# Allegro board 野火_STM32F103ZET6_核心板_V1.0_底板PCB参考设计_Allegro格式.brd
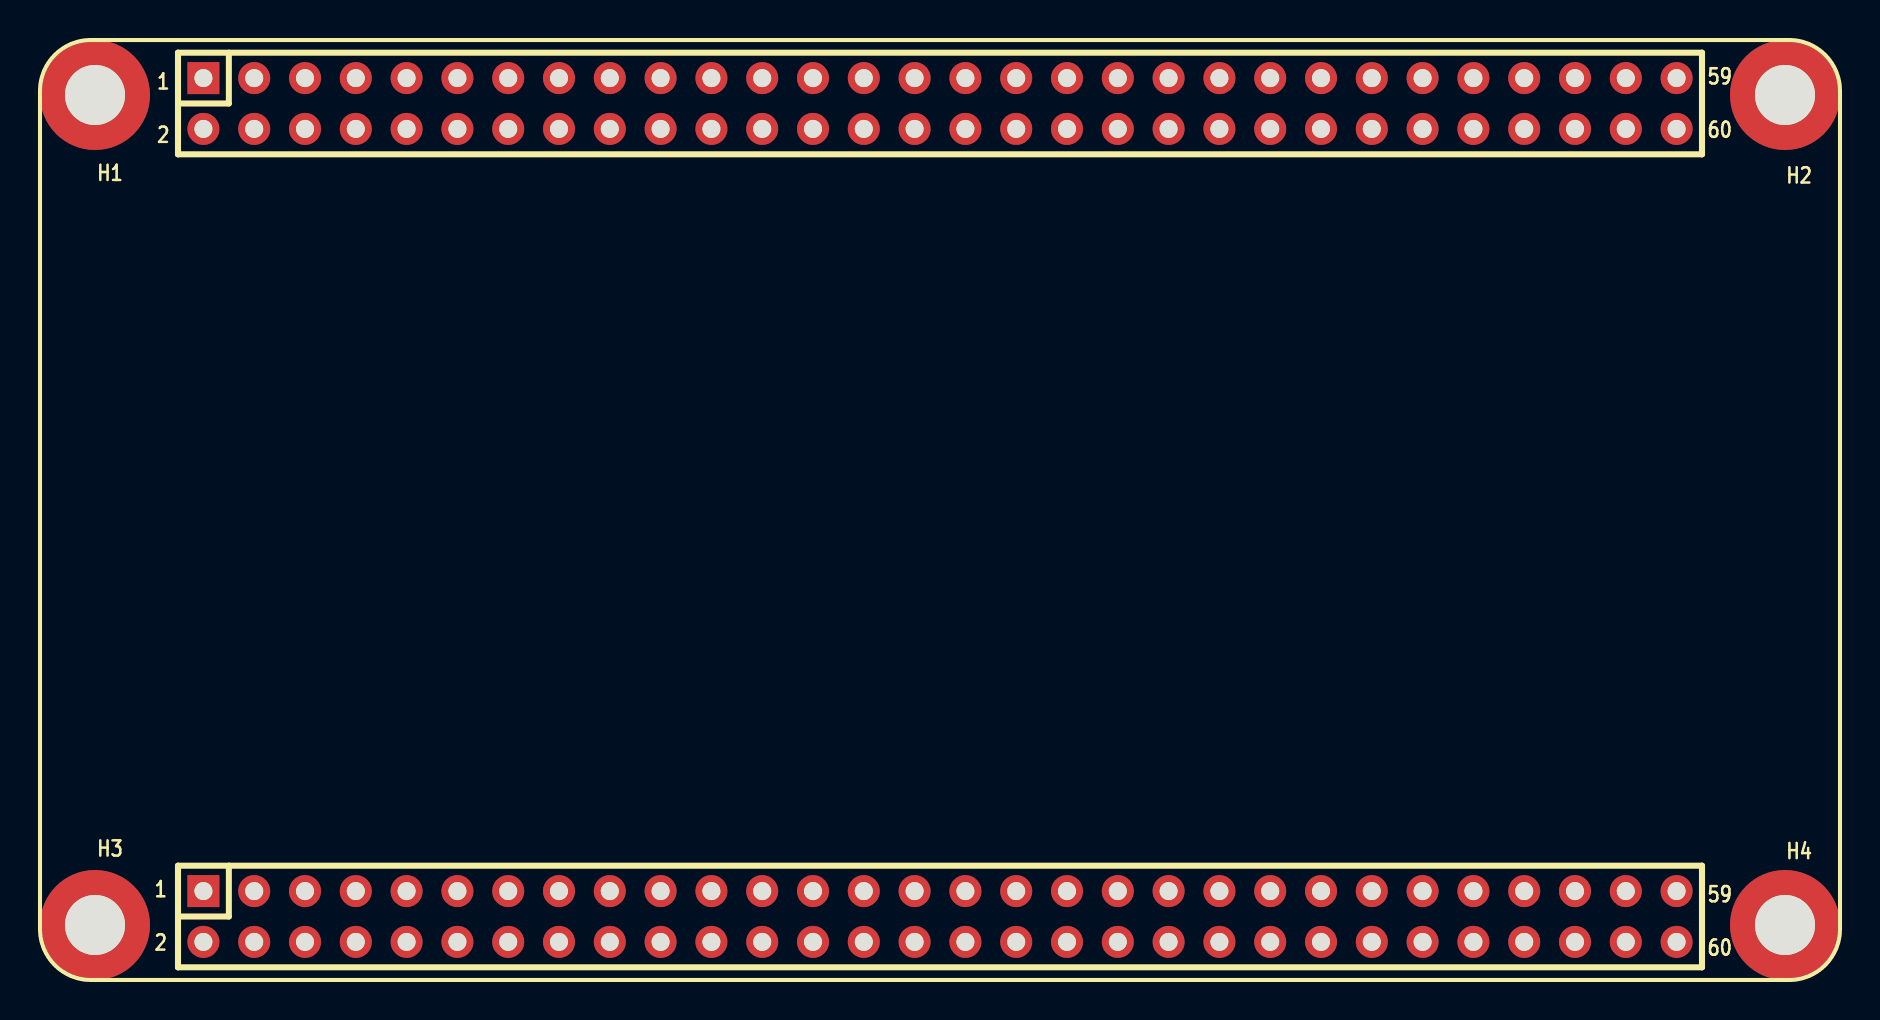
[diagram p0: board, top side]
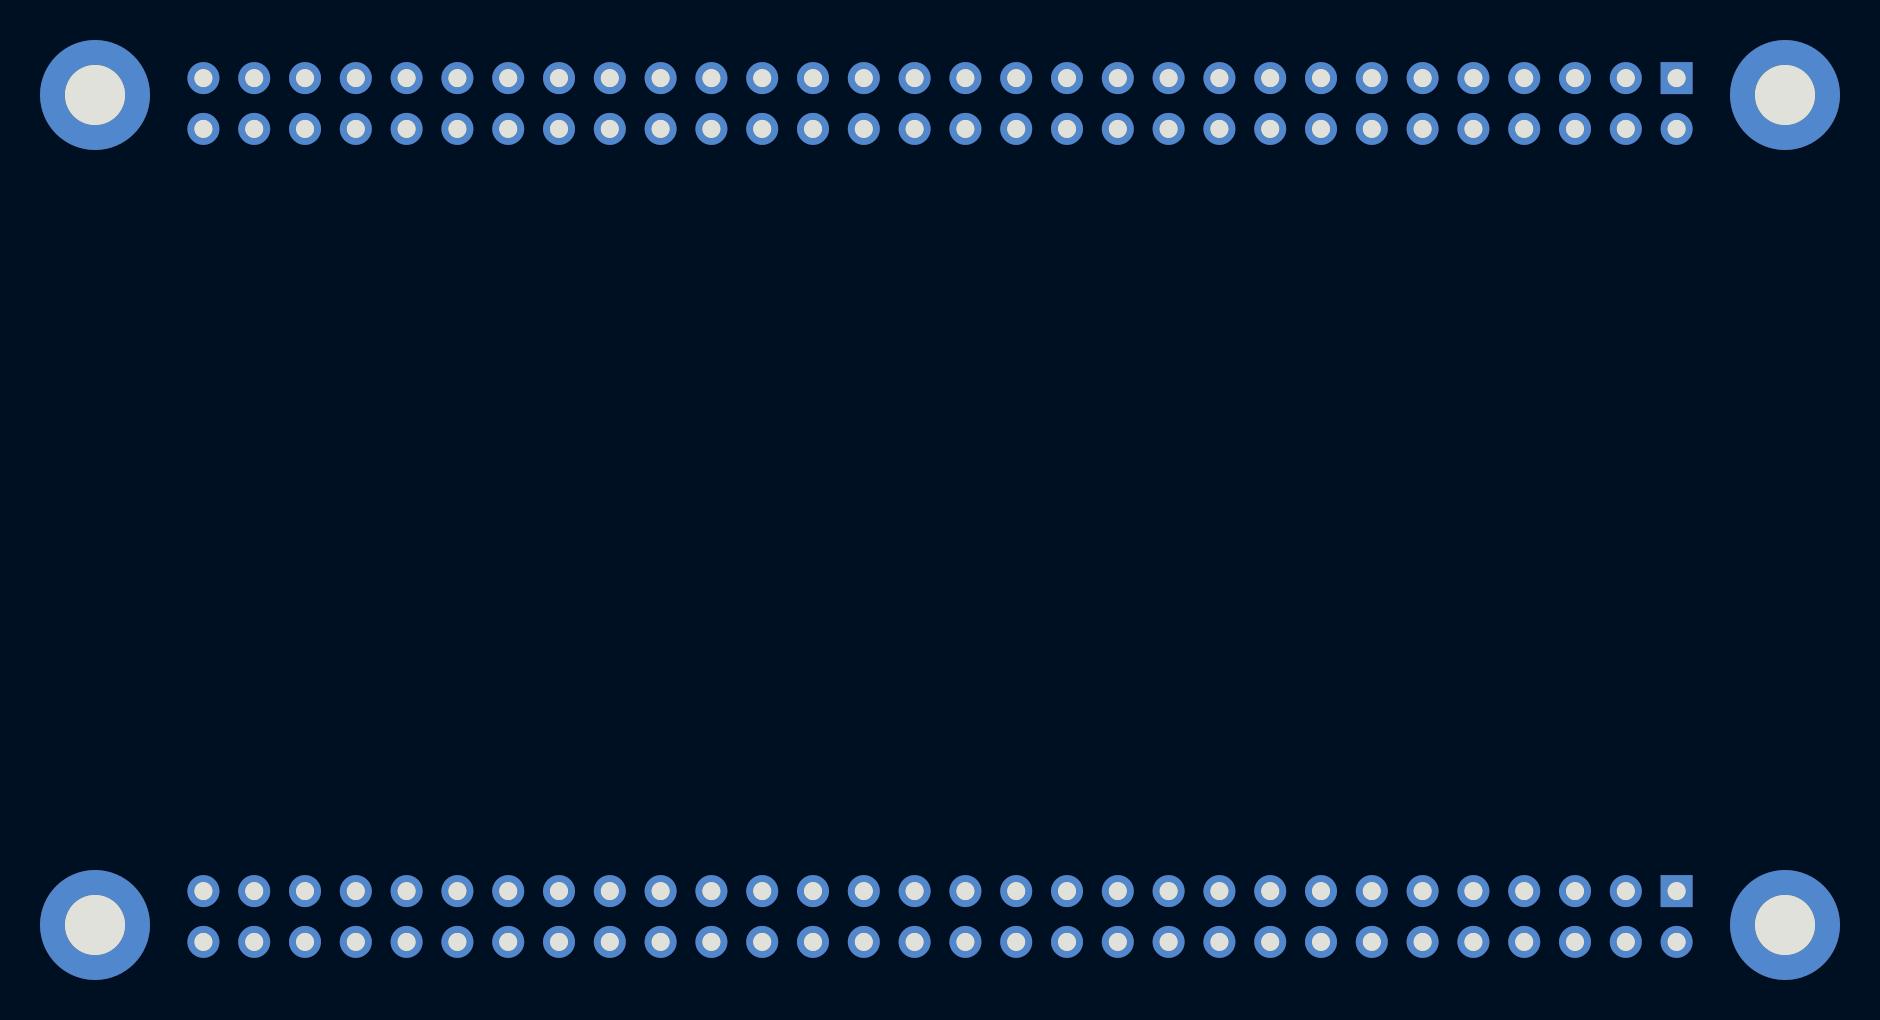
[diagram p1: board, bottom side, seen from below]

No outline. copper layers: TOP, BOTTOM. Coordinates in mm from the lowest, leftmost part position.

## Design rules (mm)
net group USB_DIFF: nets PA11 PA12
net group PWR: nets 3V3 GND VBAT

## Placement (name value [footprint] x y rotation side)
CN2  DIP_2X30_2P54  [DIP-2X302P54]  45 3.17 0 bottom
CN3  DIP_2X30_2P54  [DIP-2X302P54]  45 43.82 0 bottom
H1  3.0mm  [T3-5P5]  2.75 44.25 0 top
H2  3.0mm  [T3-5P5]  87.25 44.25 0 top
H3  3.0mm  [T3-5P5]  2.75 2.75 0 top
H4  3.0mm  [T3-5P5]  87.25 2.75 0 top
NOREF  -  []  2.54 0 90 top
NOREF#2  -  []  0 44.46 0 top

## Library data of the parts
CN2 CN3 = DIP_2X40_0
H1-H4 = SPACER_0

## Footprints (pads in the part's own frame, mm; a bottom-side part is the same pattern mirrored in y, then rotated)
DIP-2X302P54
  rect 1.6x1.6 hole 0.9: 1(-36.83,-1.27)
  round 1.6 hole 0.9: 2(-36.83,1.27) 3(-34.29,-1.27) 4(-34.29,1.27) 5(-31.75,-1.27) 6(-31.75,1.27) 7(-29.21,-1.27) 8(-29.21,1.27) 9(-26.67,-1.27) 10(-26.67,1.27) 11(-24.13,-1.27) 12(-24.13,1.27) 13(-21.59,-1.27) 14(-21.59,1.27) 15(-19.05,-1.27) 16(-19.05,1.27) 17(-16.51,-1.27) 18(-16.51,1.27) 19(-13.97,-1.27) 20(-13.97,1.27) 21(-11.43,-1.27) 22(-11.43,1.27) 23(-8.89,-1.27) 24(-8.89,1.27) 25(-6.35,-1.27) 26(-6.35,1.27) 27(-3.81,-1.27) 28(-3.81,1.27) 29(-1.27,-1.27) 30(-1.27,1.27) 31(1.27,-1.27) 32(1.27,1.27) 33(3.81,-1.27) 34(3.81,1.27) 35(6.35,-1.27) 36(6.35,1.27) 37(8.89,-1.27) 38(8.89,1.27) 39(11.43,-1.27) 40(11.43,1.27) 41(13.97,-1.27) 42(13.97,1.27) 43(16.51,-1.27) 44(16.51,1.27) 45(19.05,-1.27) 46(19.05,1.27) 47(21.59,-1.27) 48(21.59,1.27) 49(24.13,-1.27) 50(24.13,1.27) 51(26.67,-1.27) 52(26.67,1.27) 53(29.21,-1.27) 54(29.21,1.27) 55(31.75,-1.27) 56(31.75,1.27) 57(34.29,-1.27) 58(34.29,1.27) 59(36.83,-1.27) 60(36.83,1.27)
T3-5P5
  round 5.5 hole 3: 1(0,0)

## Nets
3V3: CN2.59 CN2.60
GND: CN2.7 CN2.8 CN2.57 CN2.58 CN3.46 H1.1(NC_1) H2.1(NC_1) H3.1(NC_1) H4.1(NC_1)
VBAT: CN3.60
BOOT0: CN2.9
NRST: CN3.6
PA0/WKUP: CN2.55
PA1: CN3.59
PA2: CN2.12
PA3: CN2.14
PA4: CN2.1
PA5: CN2.2
PA6: CN2.3
PA7: CN2.4
PA8: CN3.19
PA9: CN2.11
PA10: CN2.13
PA11: CN3.37
PA12: CN3.38
PA13: CN3.3
PA14: CN3.2
PA15: CN3.1
PB0: CN2.52
PB1: CN2.53
PB2: CN2.10
PB3: CN3.4
PB4: CN3.5
PB5: CN2.51
PB6: CN2.5
PB7: CN2.6
PB8: CN3.22
PB9: CN3.24
PB10: CN3.26
PB11: CN3.28
PB12: CN3.13
PB13: CN3.8
PB14: CN3.9
PB15: CN3.10
PC0: CN3.29
PC1: CN3.32
PC2: CN3.31
PC3: CN3.15
PC4: CN3.23
PC5: CN3.17
PC6: CN3.27
PC7: CN3.30
PC8: CN3.53
PC9: CN3.55
PC10: CN3.57
PC11: CN3.54
PC12: CN3.58
PC13/TAMPER: CN2.56
PD0: CN2.37
PD1: CN2.38
PD2: CN3.56
PD3: CN3.20
PD4: CN3.41
PD5: CN3.42
PD6: CN3.18
PD7: CN3.52
PD8: CN2.48
PD9: CN2.49
PD10: CN2.50
PD11: CN2.31
PD12: CN2.32
PD13: CN2.33
PD14: CN2.35
PD15: CN2.36
PE0: CN3.43
PE1: CN3.44
PE2: CN3.39
PE3: CN3.14
PE4: CN3.25
PE5: CN3.21
PE6: CN3.16
PE7: CN2.39
PE8: CN2.40
PE9: CN2.41
PE10: CN2.42
PE11: CN2.43
PE12: CN2.44
PE13: CN2.45
PE14: CN2.46
PE15: CN2.47
PF0: CN2.15
PF1: CN2.16
PF2: CN2.17
PF3: CN2.18
PF4: CN2.19
PF5: CN2.20
PF6: CN3.34
PF7: CN3.36
PF8: CN2.54
PF9: CN3.47
PF10: CN3.49
PF11: CN3.50
PF12: CN2.21
PF13: CN2.22
PF14: CN2.23
PF15: CN2.24
PG0: CN2.25
PG1: CN2.26
PG2: CN2.27
PG3: CN2.28
PG4: CN2.29
PG5: CN2.30
PG6: CN3.35
PG7: CN3.33
PG8: CN3.11
PG9: CN3.7
PG10: CN3.40
PG11: CN3.48
PG12: CN2.34
PG13: CN3.45
PG14: CN3.51
PG15: CN3.12

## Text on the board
User.Comments: R | BOOT0 | 3V3 | GND | 5V | BOOT1 | RESET | RXD | TXD | TMS | TCK | RST | KEY2 | KEY1 | PA10 | PF12 | PF14 | PD11 | PD13 | PD14 | PE11 | PE13 | PE15 | PA4 | PA6 | PB6 | PA9 | PF0 | PF2 | PF4 | PG0 | PG2 | PG4 | PD0 | PE7 | PE9 | PD9 | PB5 | PB1 | PA0 | PF13 | PF15 | PD12 | PG12 | PD15 | PE10 | PE12 | PE14 | PD10 | PC13 | PA5 | PA7 | PB7 | PB2 | PA2 | PA3 | PF1 | PF3 | PF5 | PG1 | PG3 | PG5 | PD1 | PE8 | PD8 | PB0 | PF8 | PA15 | PA13 | PB14 | PB12 | PA11 | PG13 | PF10 | PG14 | PC10 | PB4 | PG9 | PG8 | PC3 | PC5 | PA8 | PE5 | PC4 | PE4 | PC6 | PC0 | PC2 | PG7 | PG6 | PE2 | PD4 | PE0 | PF9 | PC8 | PC9 | PA1 | PA14 | NRST | PB13 | PB15 | PG15 | PB10 | PB11 | PA12 | PG10 | PG11 | PF11 | PC11 | PC12 | VBAT | PB3 | PE3 | PE6 | PD6 | PD3 | PB8 | PB9 | PC7 | PC1 | PF6 | PF7 | PD5 | PE1 | PD7 | PD2 | A | STM32F103ZET6 | B
Ref Des/Silkscreen Top: 1 | 2 | 59 | 60
NCLEGEND-1-2: FIGURE | SIZE | 8.0 | 10.0 | 31.5 | 35.43 | 118.11 | 40.0 | 47.24x19.69 | DRILL CHART: TOP to BOTTOM | ALL UNITS ARE IN MILS | PLATED | NON-PLATED | QTY | 275 | 118 | 2 | 134 | 8 | 4
